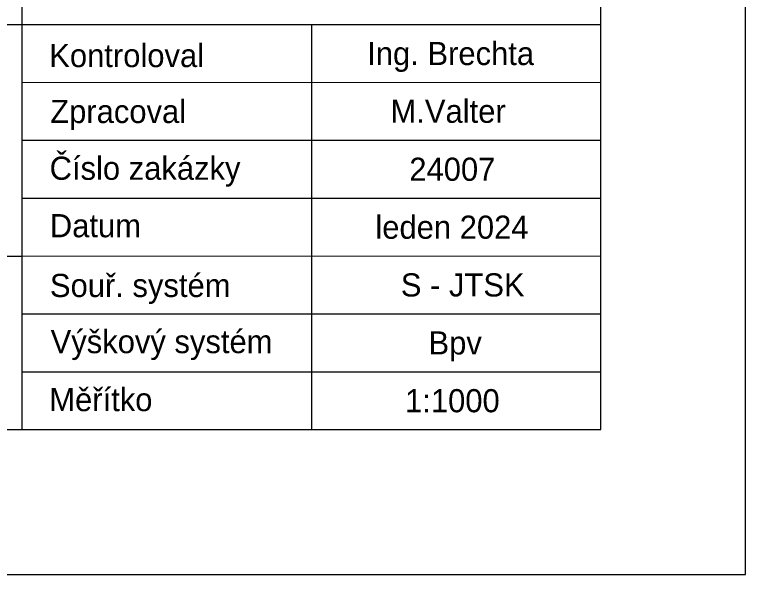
# Model space of a CAD drawing. Extents: x -590420 to -590210, y -1129531 to -1129234.
# Drawn here: x -590286.2 to -590210.4, y -1129530.9 to -1129472.8 of the extents above; entities that cross this region are included whole.
import ezdxf

# ---------------------------------------------------------------- set-up
doc = ezdxf.new("R2010")
doc.units = 0
doc.layers.add('Vrstva 63', color=7, linetype='Continuous')

msp = doc.modelspace()

# ---------------------------------------------------------------- linework, layer by layer
at = {"layer": 'Vrstva 63'}
for p, q in [((-590210.408, -1129530.852), (-590210.408, -1129233.852)), ((-590285.404, -1129515.853), (-590285.412, -1129455.85)), ((-590225.413, -1129515.851), (-590225.412, -1129455.855)), ((-590225.413, -1129515.851), (-590225.412, -1129455.855)), ((-590405.41, -1129473.846), (-590285.409, -1129473.859)), ((-590285.409, -1129473.859), (-590225.41, -1129473.852)), ((-590255.411, -1129473.85), (-590255.407, -1129479.836)), ((-590285.408, -1129479.85), (-590255.407, -1129479.836)), ((-590255.407, -1129479.836), (-590255.402, -1129485.851)), ((-590255.407, -1129479.836), (-590225.412, -1129479.852)), ((-590285.41, -1129485.85), (-590255.402, -1129485.851)), ((-590255.402, -1129485.851), (-590255.406, -1129491.867)), ((-590255.402, -1129485.851), (-590225.411, -1129485.85)), ((-590285.404, -1129491.852), (-590255.406, -1129491.867)), ((-590255.406, -1129491.867), (-590225.411, -1129491.858)), ((-590255.406, -1129491.867), (-590255.404, -1129497.841)), ((-590405.41, -1129497.851), (-590285.402, -1129497.855)), ((-590285.402, -1129497.855), (-590255.404, -1129497.841)), ((-590255.404, -1129497.841), (-590255.404, -1129503.853)), ((-590255.404, -1129497.841), (-590225.41, -1129497.853)), ((-590285.404, -1129503.854), (-590255.404, -1129503.853)), ((-590255.404, -1129503.853), (-590255.408, -1129509.869)), ((-590255.404, -1129503.853), (-590225.408, -1129503.855)), ((-590285.411, -1129509.851), (-590255.408, -1129509.869)), ((-590255.408, -1129509.869), (-590225.411, -1129509.851)), ((-590255.408, -1129509.869), (-590255.404, -1129515.855)), ((-590405.408, -1129515.852), (-590225.413, -1129515.851)), ((-590405.408, -1129515.852), (-590225.413, -1129515.851)), ((-590420.408, -1129530.852), (-590210.408, -1129530.852))]:
    msp.add_line(p, q, dxfattribs=at)

# ---------------------------------------------------------------- texts
for s, p in [('Kontroloval', (-590282.601, -1129478.27)), ('Ing. Brechta', (-590249.627, -1129478.059)), ('Zpracoval', (-590282.501, -1129484.066)), ('M.Valter', (-590247.213, -1129484.044)), ('Číslo zakázky', (-590282.565, -1129489.952)), ('24007', (-590245.26, -1129490.057)), ('Datum', (-590282.54, -1129495.906)), ('leden 2024', (-590248.781, -1129496.063)), ('Souř. systém', (-590282.532, -1129502.102)), ('S - JTSK', (-590246.139, -1129502.048)), ('Výškový systém', (-590282.458, -1129507.924)), ('Bpv', (-590243.271, -1129508.056)), ('Měřítko', (-590282.6, -1129513.934)), ('1:1000', (-590245.701, -1129514.05))]:
    msp.add_text(s, height=2.4, rotation=0.0005, dxfattribs=at).set_placement(p)

doc.saveas('drawing.dxf')
